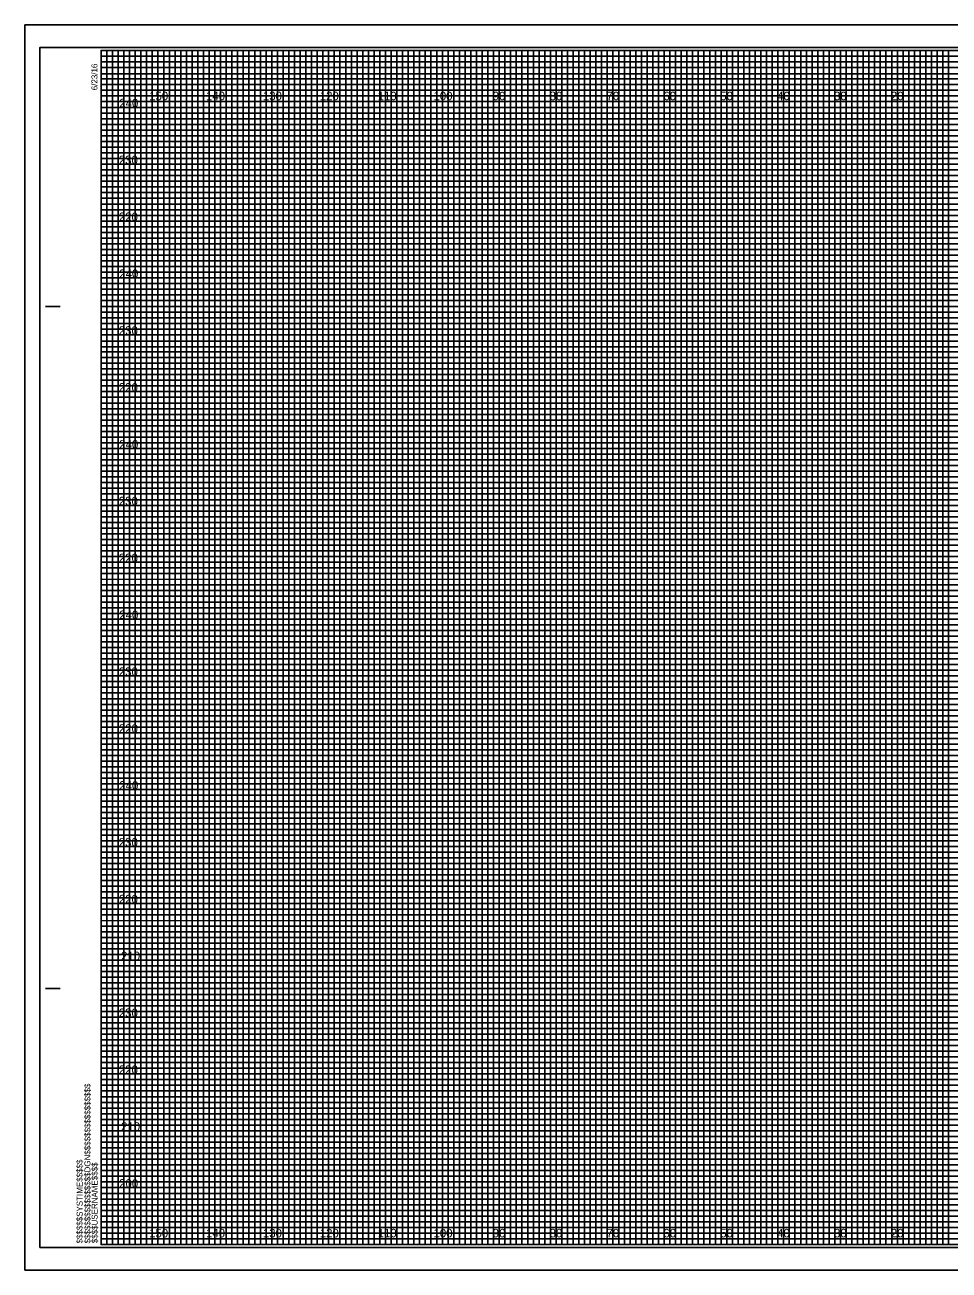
# Model space of a CAD drawing. Extents: x -13 to 359, y -5 to 2854.
# Drawn here: x -13.4 to 149.1, y 1095.5 to 1314.5 of the extents above; entities that cross this region are included whole.
import ezdxf

# ---------------------------------------------------------------- set-up
doc = ezdxf.new("R2010")
doc.units = 0
for name, color, linetype in [('Exist Cross Section Cell', 7, 'Continuous'), ('Exist XS Ground Line', 7, 'Continuous'), ('Prop CMT Concrete Structures', 7, 'Continuous'), ('Prop CMT DNC', 7, 'Continuous'), ('Prop CMT Pvmt Course 1', 7, 'Continuous'), ('Prop CMT Pvmt Course 1 CG', 7, 'Continuous'), ('Prop CMT Pvmt Course 2', 7, 'Continuous'), ('Prop CMT Shear Line', 7, 'Continuous'), ('Prop CMT Slope Grass', 7, 'Continuous'), ('Prop CMT Subgrade Earthwork', 7, 'Continuous'), ('Scratch_Level_0', 7, 'Continuous')]:
    doc.layers.add(name, color=color, linetype=linetype)

msp = doc.modelspace()

# ---------------------------------------------------------------- linework, layer by layer
at = {"layer": 'Exist XS Ground Line'}
for p, q in [((10, 1310), (0, 1310)), ((10, 1100), (10, 1310)), ((30, 1310), (20, 1310)), ((20, 1310), (20, 1100)), ((30, 1100), (30, 1310)), ((50, 1310), (40, 1310)), ((40, 1310), (40, 1100)), ((50, 1100), (50, 1310)), ((70, 1310), (60, 1310)), ((60, 1310), (60, 1100)), ((70, 1100), (70, 1310)), ((90, 1310), (80, 1310)), ((80, 1310), (80, 1100)), ((90, 1100), (90, 1310)), ((110, 1310), (100, 1310)), ((100, 1310), (100, 1100)), ((110, 1100), (110, 1310)), ((130, 1310), (120, 1310)), ((120, 1310), (120, 1100)), ((130, 1100), (130, 1310)), ((150, 1310), (140, 1310)), ((140, 1310), (140, 1100)), ((20, 1100), (10, 1100)), ((40, 1100), (30, 1100)), ((60, 1100), (50, 1100)), ((80, 1100), (70, 1100)), ((100, 1100), (90, 1100)), ((120, 1100), (110, 1100)), ((140, 1100), (130, 1100))]:
    msp.add_line(p, q, dxfattribs=at)
for points in [[(0, 1300), (320, 1300), (320, 1290), (0, 1290)], [(0, 1280), (320, 1280), (320, 1270), (0, 1270)], [(0, 1260), (320, 1260), (320, 1250), (0, 1250)], [(0, 1240), (320, 1240), (320, 1230), (0, 1230)], [(0, 1220), (320, 1220), (320, 1210), (0, 1210)], [(0, 1200), (320, 1200), (320, 1190), (0, 1190)], [(0, 1180), (320, 1180), (320, 1170), (0, 1170)], [(0, 1160), (320, 1160), (320, 1150), (0, 1150)], [(0, 1140), (320, 1140), (320, 1130), (0, 1130)], [(0, 1120), (320, 1120), (320, 1110), (0, 1110)]]:
    msp.add_lwpolyline(points, dxfattribs=at)
at = {"layer": 'Prop CMT Concrete Structures'}
for p, q in [((-9.8, 1265), (-7.3, 1265)), ((-9.7, 1265), (-7.2, 1265)), ((-9.8, 1145), (-7.3, 1145)), ((-9.7, 1145), (-7.2, 1145)), ((0, 1100), (0, 1100)), ((0, 1100), (0, 1100)), ((0, 1100), (0, 1100)), ((0, 1100), (0, 1100)), ((0, 1100), (0, 1100)), ((0, 1100), (0, 1100)), ((0, 1100), (0, 1100))]:
    msp.add_line(p, q, dxfattribs=at)
msp.add_lwpolyline([(320, 1310), (0, 1310), (0, 1100), (320, 1100)], close=True, dxfattribs=at)
at = {"layer": 'Prop CMT DNC'}
for p, q in [((323.3, 1314.5), (-13.4, 1314.5)), ((-13.4, 1314.5), (-13.4, 1095.5)), ((-13.4, 1095.5), (323.3, 1095.5))]:
    msp.add_line(p, q, dxfattribs=at)
at = {"layer": 'Prop CMT Pvmt Course 1'}
for p, q in [((0, 1309), (260, 1309)), ((260, 1307.98), (0, 1307.98)), ((0, 1307.98), (0, 1307)), ((0, 1307), (260, 1307)), ((260, 1305.89), (0, 1305.89)), ((0, 1305.89), (0, 1304)), ((0, 1304), (320, 1304))]:
    msp.add_line(p, q, dxfattribs=at)
for points in [[(0, 1303), (270, 1303), (320, 1303), (320, 1302), (0, 1302)], [(0, 1301), (320, 1301), (320, 1299), (0, 1299)], [(0, 1298), (320, 1298), (320, 1297), (0, 1296.98)], [(0, 1296), (320, 1296), (320, 1294), (0, 1294)], [(0, 1293), (320, 1293), (320, 1292), (0, 1292)], [(0, 1291), (320, 1291), (320, 1289), (0, 1289)], [(0, 1288), (320, 1288), (320, 1287), (0, 1287)], [(0, 1286), (320, 1286), (320, 1284), (0, 1284)], [(0, 1283), (320, 1283), (320, 1282), (0, 1282)], [(0, 1281), (320, 1281), (320, 1279), (0, 1279)], [(0, 1278), (320, 1278), (320, 1277), (0, 1277)], [(0, 1276), (320, 1276), (320, 1273.95), (320, 1273), (320, 1272), (0, 1272)], [(0, 1274), (320, 1274), (320, 1273), (0, 1273)], [(0, 1271), (320, 1271), (320, 1269), (0, 1269.03)], [(0, 1269.03), (320, 1269), (320, 1268), (0, 1268)], [(0, 1267), (320, 1267), (320, 1266), (0, 1266)], [(0, 1264), (320, 1264), (320, 1263), (0, 1263)], [(0, 1262), (320, 1262), (320, 1261), (0, 1261)], [(-0.07, 1258.89), (320, 1258.89), (320, 1257.88), (-0.07, 1257.88)], [(0, 1257), (320, 1257), (320, 1256), (0, 1256)], [(0, 1254), (320, 1254), (320, 1253), (0, 1253)], [(0, 1252), (320, 1252), (320, 1251), (0, 1251)], [(0, 1249), (320, 1249), (320, 1248), (0, 1248)], [(0, 1247), (320, 1247), (320, 1246), (0, 1246)], [(0, 1244), (320, 1244), (320, 1243), (0, 1243)], [(0, 1242), (320, 1242), (320, 1241), (0, 1241)], [(0, 1239), (320, 1239), (319.99, 1237.98), (0, 1238)], [(0, 1237), (320, 1237), (320, 1236), (0, 1236)], [(0, 1234), (320, 1234), (320, 1233), (0, 1233)], [(0, 1232), (320, 1232), (320, 1231), (0, 1231)], [(0, 1229), (320, 1229), (320, 1228), (0, 1228)], [(0, 1227), (320, 1227), (320, 1226), (0, 1226)], [(0, 1224), (320, 1224), (320, 1223), (0, 1223)], [(0, 1222), (320, 1222), (320, 1221), (0, 1221)], [(0, 1219), (320, 1219), (320, 1218), (0, 1218)], [(0, 1216.99), (320.07, 1216.91), (320, 1216), (0, 1216)], [(0, 1214), (320, 1214), (320, 1213), (0, 1213)], [(0, 1212), (320, 1212), (320, 1211), (0, 1211)], [(0, 1209), (320, 1209), (320, 1208), (0, 1208)], [(0, 1207), (320, 1207), (320, 1206), (0, 1206)], [(0, 1204), (320, 1204), (320, 1203), (0, 1203)], [(0, 1202), (320, 1202), (320, 1201), (0, 1201)], [(0, 1199), (320, 1199), (320, 1198), (0, 1198)], [(0, 1197), (320, 1197), (320, 1196), (0, 1196)], [(0, 1194), (320, 1194), (320, 1193), (0, 1193)], [(0, 1192), (320, 1192), (320, 1191), (0, 1191)], [(0, 1189), (320, 1189), (320, 1188), (0, 1188)], [(0, 1187), (320, 1187), (320, 1186), (0, 1186)], [(0, 1184), (320, 1184), (320, 1183), (0, 1183)], [(0, 1182), (320, 1182), (320, 1181), (0, 1181)], [(0, 1179), (320, 1179), (319.99, 1177.98), (0, 1178)], [(0, 1177), (320, 1177), (320, 1176), (0, 1176)], [(0, 1174), (320, 1174), (320, 1173), (0, 1173)], [(0, 1172), (320, 1172), (320, 1171), (0, 1171)], [(0, 1169), (320, 1169), (320, 1168), (0, 1168)], [(0, 1167), (320, 1167), (320, 1166), (0, 1166)], [(0, 1164), (320, 1164), (320, 1163), (0, 1163)], [(0, 1162), (320, 1162), (320, 1161), (0, 1161)], [(0, 1159), (320, 1159), (320, 1158), (0, 1158)], [(0, 1156.99), (320.07, 1156.91), (320, 1156), (0, 1156)], [(0, 1154), (320, 1154), (320, 1153), (0, 1153)], [(0, 1152), (320, 1152), (320, 1151), (0, 1151)], [(0, 1149), (320, 1149), (320, 1148), (0, 1148)], [(0, 1147), (320, 1147), (320, 1146), (0, 1146)], [(0, 1144), (320, 1144), (320, 1143), (0, 1143)], [(0, 1142), (320, 1142), (320, 1141), (0, 1141)], [(0, 1139), (320, 1139), (320, 1138), (0, 1138)], [(0, 1137), (320, 1137), (320, 1136), (0, 1136)], [(0, 1134), (320, 1134), (320, 1133), (0, 1133)], [(0, 1132), (320, 1132), (320, 1131), (0, 1131)], [(0, 1129), (320, 1129), (320, 1128), (0, 1128)], [(0, 1127), (320, 1127), (320, 1126), (0, 1126)], [(0, 1124), (320, 1124), (320, 1123), (0, 1123)], [(0, 1122), (320, 1122), (320, 1121), (0, 1121)], [(0, 1119), (320, 1119), (320, 1118), (0, 1118)], [(0, 1117), (320, 1117), (320, 1116), (0, 1116)], [(0, 1114), (320, 1114), (320, 1113), (0, 1113)], [(0, 1112), (320, 1112), (320, 1111), (0, 1111)], [(0, 1109), (320, 1109), (320, 1108), (0, 1108)], [(0, 1107), (320, 1107), (320, 1106), (0, 1106)], [(0, 1104), (320, 1104), (320, 1103), (0, 1103)], [(0, 1102), (320, 1102), (320, 1101), (0, 1101)]]:
    msp.add_lwpolyline(points, dxfattribs=at)
at = {"layer": 'Prop CMT Pvmt Course 1 CG'}
for points in [[(0, 1100), (1, 1100), (1, 1310), (2, 1310), (2, 1100)], [(2, 1100), (3, 1100), (3, 1310), (4, 1310), (4, 1100)], [(5, 1100), (6, 1100), (6, 1310), (7, 1310), (7, 1100)], [(7, 1100), (8, 1100), (8, 1310), (9, 1310), (9, 1100)], [(10, 1100), (11, 1100), (11, 1310), (12, 1310), (12, 1100)], [(12, 1100), (13, 1100), (13, 1310), (14, 1310), (14, 1100)], [(15, 1100), (16, 1100), (16, 1310), (17, 1310), (17, 1100)], [(17, 1100), (18, 1100), (18, 1310), (19, 1310), (19, 1100)], [(20, 1100), (21, 1100), (21, 1310), (22, 1310), (22, 1100)], [(22, 1100), (23, 1100), (23, 1310), (24, 1310), (24, 1100)], [(25, 1100), (26, 1100), (26, 1310), (27, 1310), (27, 1100)], [(27, 1100), (28, 1100), (28, 1310), (29, 1310), (29, 1100)], [(30, 1100), (31, 1100), (31, 1310), (32, 1310), (32, 1100)], [(32, 1100), (33, 1100), (33, 1310), (34, 1310), (34, 1100)], [(35, 1100), (36, 1100), (36, 1310), (37, 1310), (37, 1100)], [(37, 1100), (38, 1100), (38, 1310), (39, 1310), (39, 1100)], [(40, 1100), (41, 1100), (41, 1310), (42, 1310), (42, 1100)], [(42, 1100), (43, 1100), (43, 1310), (44, 1310), (44, 1100)], [(45, 1100), (46, 1100), (46, 1310), (47, 1310), (47, 1100)], [(47, 1100), (48, 1100), (48, 1310), (49, 1310), (49, 1100)], [(50, 1100), (51, 1100), (51, 1310), (52, 1310), (52, 1100)], [(52, 1100), (53, 1100), (53, 1310), (54, 1310), (54, 1100)], [(55, 1100), (56, 1100), (56, 1310), (57, 1310), (57, 1100)], [(57, 1100), (58, 1100), (58, 1310), (59, 1310), (59, 1100)], [(60, 1100), (61, 1100), (61, 1310), (62, 1310), (62, 1100)], [(62, 1100), (63, 1100), (63, 1310), (64, 1310), (64, 1100)], [(65, 1100), (66, 1100), (66, 1310), (67, 1310), (67, 1100)], [(67, 1100), (68, 1100), (68, 1310), (69, 1310), (69, 1100)], [(70, 1100), (71, 1100), (71, 1310), (72, 1310), (72, 1100)], [(72, 1100), (73, 1100), (73, 1310), (74, 1310), (74, 1100)], [(75, 1100), (76, 1100), (76, 1310), (77, 1310), (77, 1100)], [(77, 1100), (78, 1100), (78, 1310), (79, 1310), (79, 1100)], [(80, 1100), (81, 1100), (81, 1310), (82, 1310), (82, 1100)], [(82, 1100), (83, 1100), (83, 1310), (84, 1310), (84, 1100)], [(85, 1100), (86, 1100), (86, 1310), (87, 1310), (87, 1100)], [(87, 1100), (88, 1100), (88, 1310), (89, 1310), (89, 1100)], [(90, 1100), (91, 1100), (91, 1310), (92, 1310), (92, 1100)], [(92, 1100), (93, 1100), (93, 1310), (94, 1310), (94, 1100)], [(95, 1100), (96, 1100), (96, 1310), (97, 1310), (97, 1100)], [(97, 1100), (98, 1100), (98, 1310), (99, 1310), (99, 1100)], [(100, 1100), (101, 1100), (101, 1310), (102, 1310), (102, 1100)], [(102, 1100), (103, 1100), (103, 1310), (104, 1310), (104, 1100)], [(105, 1100), (106, 1100), (106, 1310), (107, 1310), (107, 1100)], [(107, 1100), (108, 1100), (108, 1310), (109, 1310), (109, 1100)], [(110, 1100), (111, 1100), (111, 1310), (112, 1310), (112, 1100)], [(112, 1100), (113, 1100), (113, 1310), (114, 1310), (114, 1100)], [(115, 1100), (116, 1100), (116, 1310), (117, 1310), (117, 1100)], [(117, 1100), (118, 1100), (118, 1310), (119, 1310), (119, 1100)], [(120, 1100), (121, 1100), (121, 1310), (122, 1310), (122, 1100)], [(122, 1100), (123, 1100), (123, 1310), (124, 1310), (124, 1100)], [(125, 1100), (126, 1100), (126, 1310), (127, 1310), (127, 1100)], [(127, 1100), (128, 1100), (128, 1310), (129, 1310), (129, 1100)], [(130, 1100), (131, 1100), (131, 1310), (132, 1310), (132, 1100)], [(132, 1100), (133, 1100), (133, 1310), (134, 1310), (134, 1100)], [(135, 1100), (136, 1100), (136, 1310), (137, 1310), (137, 1100)], [(137, 1100), (138, 1100), (138, 1310), (139, 1310), (139, 1100)], [(140, 1100), (141, 1100), (141, 1310), (142, 1310), (142, 1100)], [(142, 1100), (143, 1100), (143, 1310), (144, 1310), (144, 1100)], [(145, 1100), (146, 1100), (146, 1310), (147, 1310), (147, 1100)], [(147, 1100), (148, 1100), (148, 1310), (149, 1310), (149, 1100)]]:
    msp.add_lwpolyline(points, dxfattribs=at)
at = {"layer": 'Prop CMT Shear Line'}
for p, q in [((10, 1100), (10, 1310)), ((20, 1100), (20, 1310)), ((30, 1100), (30, 1310)), ((40, 1100), (40, 1310)), ((50, 1100), (50, 1310)), ((60, 1100), (60, 1310)), ((70, 1100), (70, 1310)), ((80, 1100), (80, 1310)), ((90, 1100), (90, 1310)), ((100, 1100), (100, 1310)), ((110, 1100), (110, 1310)), ((120, 1100), (120, 1310)), ((130, 1100), (130, 1310)), ((140, 1100), (140, 1310)), ((0, 1300), (320, 1300)), ((0, 1290), (320, 1290)), ((0, 1280), (320, 1280)), ((0, 1270), (320, 1270)), ((0, 1260), (320, 1260)), ((0, 1250), (320, 1250)), ((0, 1240), (320, 1240)), ((0, 1230), (320, 1230)), ((0, 1220), (320, 1220)), ((0, 1210), (320, 1210)), ((0, 1200), (320, 1200)), ((0, 1190), (320, 1190)), ((0, 1180), (320, 1180)), ((0, 1170), (320, 1170)), ((0, 1160), (320, 1160)), ((0, 1150), (320, 1150)), ((0, 1140), (320, 1140)), ((0, 1130), (320, 1130)), ((0, 1120), (320, 1120)), ((0, 1110), (320, 1110))]:
    msp.add_line(p, q, dxfattribs=at)
at = {"layer": 'Prop CMT Slope Grass'}
msp.add_lwpolyline([(-10.8, 1099.5), (322.4, 1099.5), (322.4, 1310.5), (-10.8, 1310.5)], close=True, dxfattribs=at)
at = {"layer": 'Prop CMT Subgrade Earthwork'}
msp.add_lwpolyline([(-13.4, 1095.5), (323.3, 1095.5), (323.3, 1314.5), (-13.4, 1314.5)], close=True, dxfattribs=at)
at = {"layer": 'Scratch_Level_0'}
for points in [[(0, 1310), (5, 1310), (5, 1100), (15, 1100), (15, 1310), (25, 1310), (25, 1100), (35, 1100), (35, 1310), (45, 1310), (45, 1100), (55, 1100), (55, 1310), (65, 1310), (65, 1100), (75, 1100), (75, 1310), (85, 1310), (85, 1100), (95, 1100), (95, 1310), (105, 1310), (105, 1100), (115, 1100), (115, 1310), (125, 1310), (125, 1100), (135, 1100), (135, 1310), (145, 1310), (145, 1100), (155, 1100)], [(0, 1305), (275, 1305)], [(0, 1285), (320, 1285), (320, 1295), (0, 1295)], [(0, 1265), (320, 1265), (320, 1275), (0, 1275)], [(0, 1245), (320, 1245), (320, 1255), (0, 1255)], [(0, 1225), (320, 1225), (320, 1235), (0, 1235)], [(0, 1205), (320, 1205), (320, 1215), (0, 1215)], [(0, 1185), (320, 1185), (320, 1195), (0, 1195)], [(0, 1165), (320, 1165), (320, 1175), (0, 1175)], [(0, 1145), (320, 1145), (320, 1155), (0, 1155)], [(0, 1125), (320, 1125), (320, 1135), (0, 1135)], [(0, 1105), (320, 1105), (320, 1115), (0, 1115)]]:
    msp.add_lwpolyline(points, dxfattribs=at)

# ---------------------------------------------------------------- texts
at = {"layer": 'Exist Cross Section Cell'}
for s, p in [('150', (8.44, 1301.25)), ('140', (18.44, 1301.25)), ('130', (28.44, 1301.25)), ('120', (38.44, 1301.25)), ('110', (48.62, 1301.25)), ('100', (58.44, 1301.25)), ('90', (68.86, 1301.25)), ('80', (78.86, 1301.25)), ('70', (88.86, 1301.25)), ('60', (98.86, 1301.25)), ('50', (108.86, 1301.25)), ('40', (118.86, 1301.25)), ('30', (128.86, 1301.25)), ('20', (138.86, 1301.25)), ('150', (8.44, 1101.25)), ('140', (18.44, 1101.25)), ('130', (28.44, 1101.25)), ('120', (38.44, 1101.25)), ('110', (48.62, 1101.25)), ('100', (58.44, 1101.25)), ('90', (68.86, 1101.25)), ('80', (78.86, 1101.25)), ('70', (88.86, 1101.25)), ('60', (98.86, 1101.25)), ('50', (108.86, 1101.25)), ('40', (118.86, 1101.25)), ('30', (128.86, 1101.25)), ('20', (138.86, 1101.25))]:
    msp.add_text(s, height=1.5, dxfattribs=at).set_placement(p)
at = {"layer": 'Prop CMT Concrete Structures'}
for s, p in [('6/23/16', (-0.65, 1303)), ('$$$$$$$$$$$$$$$$DGN$$$$$$$$$$$$$$$$', (-1.88, 1100.18)), ('$$$$$$SYSTIME$$$$$', (-3.26, 1100.18)), ('$$$$USERNAME$$$$', (-0.62, 1100.23))]:
    msp.add_text(s, height=1.05, rotation=90, dxfattribs=at).set_placement(p)
at = {"layer": 'Prop CMT Pvmt Course 2'}
for s, p in [('240', (3.19, 1300)), ('230', (3.11, 1290)), ('220', (3.12, 1280)), ('240', (3.19, 1270)), ('230', (3.11, 1260)), ('220', (3.12, 1250)), ('240', (3.19, 1240)), ('230', (3.11, 1230)), ('220', (3.12, 1220)), ('240', (3.19, 1210)), ('230', (3.11, 1200)), ('220', (3.12, 1190)), ('240', (3.19, 1180)), ('230', (3.11, 1170)), ('220', (3.12, 1160)), ('210', (3.5, 1150)), ('230', (3.11, 1140)), ('220', (3.12, 1130)), ('210', (3.5, 1120)), ('200', (3.17, 1110))]:
    msp.add_text(s, height=1.5, dxfattribs=at).set_placement(p)

doc.saveas('drawing.dxf')
